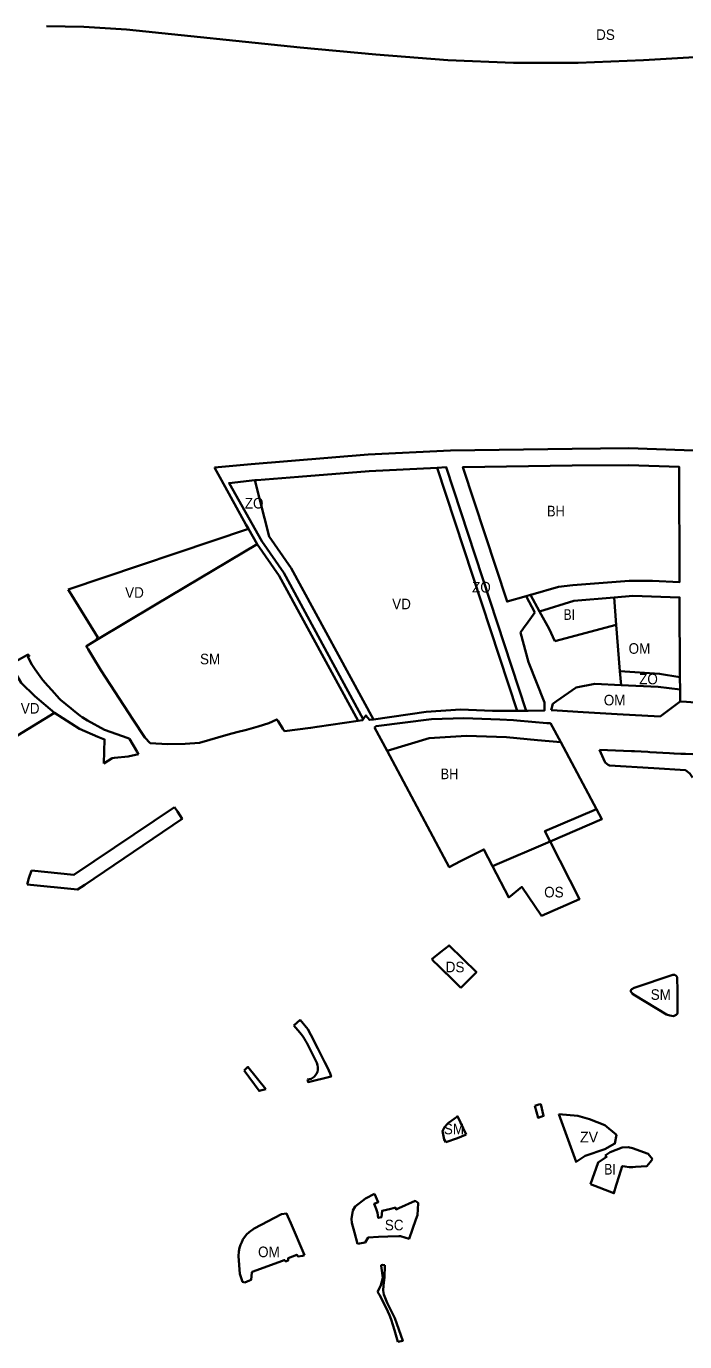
# Model space of a CAD drawing. Extents: x -650971 to -642489, y -1074311 to -1062745.
# Drawn here: x -647822 to -647077, y -1070541 to -1069053 of the extents above; entities that cross this region are included whole.
import ezdxf

# ---------------------------------------------------------------- set-up
doc = ezdxf.new("R2010")
doc.units = 0
doc.header["$LTSCALE"] = 4.8
for name, color, linetype, lineweight in [('1', 7, 'Continuous', 35), ('12', 7, 'Continuous', 35), ('15', 7, 'Continuous', 35), ('17', 7, 'Continuous', 35), ('18', 7, 'Continuous', 35), ('2', 7, 'Continuous', 35), ('24', 7, 'Continuous', 35), ('35', 7, 'Continuous', 35), ('40', 7, 'Continuous', 35), ('42', 7, 'Continuous', 35), ('62', 7, 'Continuous', 35), ('9', 7, 'Continuous', 35)]:
    doc.layers.add(name, color=color, linetype=linetype, lineweight=lineweight)

msp = doc.modelspace()

# ---------------------------------------------------------------- linework, layer by layer
at = {"layer": '1'}
msp.add_lwpolyline([(-647256.061, -1069697.32), (-647277.71, -1069703.421), (-647327.682, -1069551.263), (-647204.208, -1069549.647), (-647140.247, -1069549.071), (-647083.356, -1069551.018), (-647082.761, -1069681.399), (-647113.255, -1069679.966), (-647139.649, -1069679.961), (-647203.374, -1069684.716), (-647219.628, -1069686.746), (-647251.002, -1069695.852), (-647251.13, -1069695.888)], close=True, dxfattribs=at)
for points in [[(-647413.462, -1069872.442), (-647365.866, -1069857.774), (-647323.794, -1069855.468), (-647278.525, -1069857.002), (-647243.231, -1069860.34), (-647217.177, -1069862.57), (-647176.499, -1069938.333)], [(-647294.257, -1070002.745), (-647304.05, -1069983.79), (-647330.5, -1069997.19), (-647343.28, -1070003.81), (-647413.462, -1069872.442)], [(-647176.499, -1069938.333), (-647235, -1069963), (-647229.096, -1069974.658), (-647294.257, -1070002.745)]]:
    msp.add_lwpolyline(points, dxfattribs=at)
at = {"layer": '12'}
for points in [[(-647156.782, -1069698.901), (-647135.585, -1069697.137), (-647082.682, -1069698.791), (-647082.271, -1069788.81)], [(-647082.271, -1069788.81), (-647105.334, -1069785.168), (-647150.138, -1069782.334), (-647154.33, -1069729.69), (-647156.782, -1069698.901)], [(-647228.12, -1069826.33), (-647226.04, -1069819.17), (-647221.87, -1069816.21), (-647199.65, -1069800.69)], [(-647199.65, -1069800.69), (-647178.73, -1069796.4), (-647148.9, -1069797.88)], [(-647148.9, -1069797.88), (-647107.04, -1069799.84), (-647082.206, -1069802.916), (-647082.145, -1069816.321)], [(-647082.145, -1069816.321), (-647104.741, -1069833.568), (-647153.36, -1069830.79), (-647191.66, -1069828.58), (-647221.14, -1069826.761), (-647228.12, -1069826.33)], [(-647574.28, -1070473.46), (-647576.92, -1070473), (-647580.1, -1070463.69), (-647581.54, -1070443.7), (-647581.04, -1070438.4), (-647580.31, -1070434.48), (-647579.22, -1070431.05), (-647577.97, -1070427.92), (-647576.48, -1070425.09), (-647572.37, -1070419.41), (-647569.4, -1070416.55), (-647564.01, -1070412.59), (-647533.1, -1070396.26), (-647527.1, -1070395.72), (-647525.687, -1070399.064)], [(-647525.687, -1070399.064), (-647522.54, -1070406.51), (-647506.95, -1070442.71)], [(-647506.95, -1070442.71), (-647509.22, -1070443.62), (-647514.23, -1070444.18), (-647515.73, -1070442.32), (-647525.45, -1070446.21), (-647525.54, -1070448.89), (-647528.28, -1070449.87), (-647529.19, -1070448.53), (-647529.74, -1070448.27), (-647532.92, -1070449.43), (-647565.11, -1070461.12), (-647565.95, -1070461.58), (-647566.55, -1070462.22), (-647567.32, -1070470.66), (-647569.18, -1070471.4), (-647574.28, -1070473.46)]]:
    msp.add_lwpolyline(points, dxfattribs=at)
at = {"layer": '15'}
msp.add_line((-647518.813, -1070183.069), (-647511.73, -1070176.61), dxfattribs=at)
for points in [[(-647608.81, -1069551.868), (-647567.252, -1069548.083), (-647434.969, -1069537.141), (-647341.697, -1069532.602), (-647204.293, -1069530.647), (-647140.008, -1069530.068), (-647046.325, -1069533.275), (-646986.633, -1069539.757), (-646842.441, -1069555.283)], [(-647446.322, -1069838.338), (-647535.588, -1069674.163), (-647560.36, -1069638.39), (-647570.37, -1069621.18), (-647573.15, -1069616.16), (-647600.891, -1069566.14), (-647606.53, -1069555.98), (-647608.81, -1069551.868)], [(-647356.899, -1069552.034), (-647433.779, -1069556.106), (-647513.66, -1069562.249), (-647560.836, -1069566.036), (-647563.104, -1069566.28)], [(-647256.034, -1069827.107), (-647346.554, -1069551.486), (-647356.899, -1069552.034)], [(-647251.13, -1069695.888), (-647251.002, -1069695.852), (-647219.628, -1069686.746), (-647203.374, -1069684.716), (-647139.649, -1069679.961), (-647113.255, -1069679.966), (-647082.761, -1069681.399), (-647083.356, -1069551.018), (-647140.247, -1069549.071), (-647204.208, -1069549.647), (-647327.682, -1069551.263), (-647277.71, -1069703.421), (-647256.061, -1069697.32), (-647246.42, -1069715.63)], [(-647563.104, -1069566.28), (-647592.199, -1069569.411), (-647555.266, -1069635.207), (-647530.471, -1069671.013), (-647440.459, -1069836.56)], [(-647156.782, -1069698.901), (-647202.181, -1069702.678), (-647240.994, -1069714.513), (-647251.13, -1069695.888)], [(-647082.271, -1069788.81), (-647082.682, -1069698.791), (-647135.585, -1069697.137), (-647156.782, -1069698.901)], [(-647246.42, -1069715.63), (-647253.97, -1069726.27), (-647259.11, -1069733.52), (-647262.46, -1069738.25), (-647253.45, -1069771.95), (-647235.62, -1069817.62)], [(-647060.029, -1069817.854), (-647074.72, -1069816.8), (-647082.145, -1069816.321), (-647082.206, -1069802.916), (-647082.271, -1069788.81)], [(-647235.62, -1069817.62), (-647235.49, -1069826.51), (-647235.48, -1069826.59), (-647236.5, -1069826.63)], [(-647440.459, -1069836.56), (-647441.19, -1069837.6), (-647446.322, -1069838.338)], [(-647427.62, -1069845.94), (-647425.73, -1069844.31), (-647363.21, -1069836.64), (-647326.71, -1069835.46), (-647285.9, -1069836.66), (-647270.71, -1069837.61), (-647266.62, -1069837.86), (-647232.66, -1069841.07), (-647228.77, -1069840.98), (-647217.177, -1069862.57)], [(-647236.5, -1069826.63), (-647253.88, -1069827.12), (-647256.034, -1069827.107)], [(-647217.177, -1069862.57), (-647243.231, -1069860.34), (-647278.525, -1069857.002), (-647323.794, -1069855.468), (-647365.866, -1069857.774), (-647413.462, -1069872.442), (-647427.62, -1069845.94)], [(-647173.23, -1069871.09), (-647136.94, -1069872.55), (-647133.58, -1069872.73), (-647118.77, -1069873.51), (-647116.31, -1069873.65), (-647094.24, -1069874.85), (-647088.93, -1069875.14), (-647088.94, -1069875.34), (-647081.26, -1069875.76), (-647081.25, -1069875.56), (-647076, -1069875.85), (-647034.195, -1069877.629), (-646964.111, -1069878.315), (-646931.67, -1069902.89)], [(-647068.2, -1069902.28), (-647071, -1069897.87), (-647075.97, -1069894.33), (-647111.76, -1069891.77), (-647162.03, -1069888.89), (-647163.55, -1069887.98), (-647166.8, -1069885.63), (-647167.14, -1069884.85), (-647173.23, -1069871.09)], [(-647815.788, -1070007.72), (-647767.622, -1070012.66), (-647654.056, -1069935.903)], [(-647654.056, -1069935.903), (-647650.72, -1069940.96), (-647645.274, -1069949.279), (-647755.356, -1070023.682)], [(-647820.515, -1070023.319), (-647818.81, -1070016.41), (-647815.788, -1070007.72)], [(-647755.356, -1070023.682), (-647763.476, -1070029.17), (-647820.515, -1070023.319)], [(-647511.73, -1070176.61), (-647502.99, -1070186.94), (-647499.68, -1070193.54), (-647491.97, -1070208.95), (-647484.35, -1070223.91)], [(-647503.6, -1070243.95), (-647499.448, -1070243.223), (-647495.889, -1070240.926), (-647493.254, -1070237.6), (-647492.286, -1070235.393), (-647491.767, -1070233.217), (-647491.692, -1070229.974), (-647492.138, -1070227.681), (-647493.13, -1070225.217), (-647504.419, -1070202.575), (-647505.688, -1070200.172), (-647507.054, -1070197.854), (-647509.223, -1070194.61), (-647512.222, -1070190.785), (-647518.813, -1070183.069)], [(-647484.35, -1070223.91), (-647481.01, -1070230.53), (-647477.78, -1070237.42), (-647476.94, -1070240.79), (-647502.82, -1070246.91), (-647503.6, -1070243.95)], [(-647575.15, -1070233.71), (-647570.887, -1070229.877), (-647550.603, -1070254.911)], [(-647550.603, -1070254.911), (-647558.19, -1070256.86), (-647575.15, -1070233.71)], [(-647424.226, -1070484.029), (-647422.285, -1070480.931), (-647420.74, -1070476.57), (-647418.41, -1070468.21), (-647420.13, -1070454.78), (-647420.22, -1070454.02)], [(-647420.22, -1070454.02), (-647418.49, -1070453.76), (-647416.148, -1070454.055)], [(-647416.148, -1070454.055), (-647416.37, -1070468.064), (-647417.482, -1070476.846), (-647418.038, -1070482.516), (-647417.297, -1070487.185), (-647413.552, -1070496.671), (-647404.879, -1070514.114), (-647395.75, -1070539.47), (-647401.35, -1070540.59)], [(-647401.35, -1070540.59), (-647404.96, -1070527.57), (-647408.82, -1070515.49), (-647410.86, -1070510.68), (-647414.6, -1070502.16), (-647422.19, -1070487.75), (-647424.226, -1070484.029)]]:
    msp.add_lwpolyline(points, dxfattribs=at)
for points in [[(-647229.096, -1069974.658), (-647235, -1069963), (-647176.499, -1069938.333), (-647170.546, -1069949.42)], [(-647246.28, -1070273.733), (-647242.06, -1070272.35), (-647239.781, -1070272.031), (-647236.567, -1070285.154), (-647242.698, -1070287.238)]]:
    msp.add_lwpolyline(points, close=True, dxfattribs=at)
at = {"layer": '17'}
for points in [[(-647446.93, -1070429.99), (-647450.51, -1070416.96), (-647453.35, -1070406.09), (-647453.71, -1070401.81), (-647452.17, -1070392.38), (-647449.69, -1070387.83), (-647437.76, -1070378.66), (-647427.8, -1070373.32)], [(-647427.8, -1070373.32), (-647423.57, -1070382.64), (-647427.96, -1070384.64), (-647425.99, -1070390.47), (-647424.54, -1070394.78), (-647423.58, -1070400.59), (-647419.68, -1070399.59), (-647419.08, -1070392.52), (-647409.36, -1070390.24), (-647404, -1070388.84), (-647403.27, -1070390.91), (-647400.22, -1070389.64), (-647381.65, -1070381.45), (-647378.47, -1070383.52)], [(-647378.47, -1070383.52), (-647378.49, -1070383.91), (-647379.3, -1070397.57), (-647381.11, -1070402.45), (-647388.6, -1070424.24), (-647398.21, -1070421.15), (-647400.41, -1070421.08), (-647412.51, -1070421.5), (-647423.38, -1070421.87), (-647434.85, -1070422.64), (-647438.45, -1070428.47), (-647446.93, -1070429.99)]]:
    msp.add_lwpolyline(points, dxfattribs=at)
at = {"layer": '18'}
for points in [[(-647742.36, -1069746.93), (-647674.901, -1069706.701), (-647560.36, -1069638.39)], [(-647560.36, -1069638.39), (-647535.588, -1069674.163), (-647446.322, -1069838.338)], [(-647681.51, -1069863.72), (-647687.45, -1069857.15), (-647700.58, -1069837.2), (-647737.17, -1069780.85), (-647745.84, -1069766.71), (-647751.66, -1069757.12), (-647753.7, -1069753.9), (-647752.32, -1069752.95), (-647742.36, -1069746.93)], [(-647446.322, -1069838.338), (-647492.76, -1069845.02), (-647500.03, -1069846.28), (-647529.5, -1069849.99), (-647531.33, -1069847.23), (-647536.82, -1069838.87), (-647538.34, -1069836.68), (-647547.12, -1069840.87), (-647559.47, -1069844.92), (-647572.63, -1069848.63), (-647583.62, -1069851.13), (-647593.07, -1069853.74), (-647625.83, -1069863.19), (-647641.78, -1069864.26), (-647661.79, -1069864.92), (-647681.51, -1069863.72)], [(-647088.08, -1070125.63), (-647086.49, -1070126.62), (-647085.62, -1070128.24), (-647085.24, -1070144.07), (-647085.17, -1070154.78), (-647084.98, -1070169.29), (-647086.62, -1070170.89), (-647089.47, -1070172.21), (-647093.89, -1070171.55), (-647097.63, -1070170.37), (-647132.95, -1070149.08), (-647136.09, -1070146.97), (-647137.96, -1070144.66), (-647137.99, -1070143.09), (-647136.65, -1070141.75)], [(-647136.65, -1070141.75), (-647133.96, -1070140.44), (-647090.2, -1070125.64), (-647088.08, -1070125.63)], [(-647346.97, -1070315.05), (-647349, -1070312), (-647350.67, -1070302.55), (-647348.677, -1070297.894), (-647345.27, -1070293.99), (-647343.9, -1070292.96), (-647337.56, -1070288.43), (-647336.22, -1070287.43), (-647334.91, -1070286.51), (-647333.87, -1070285.66), (-647324.11, -1070306.21)], [(-647324.11, -1070306.21), (-647324.94, -1070306.63), (-647333.97, -1070310.22), (-647346.97, -1070315.05)]]:
    msp.add_lwpolyline(points, dxfattribs=at)
at = {"layer": '2'}
for points in [[(-647240.994, -1069714.513), (-647202.181, -1069702.678), (-647156.782, -1069698.901), (-647154.33, -1069729.69), (-647223.66, -1069748.26)], [(-647223.66, -1069748.26), (-647230.16, -1069734.42), (-647240.994, -1069714.513)], [(-647183.55, -1070362.35), (-647174.81, -1070338.01), (-647165.36, -1070331.59), (-647167.03, -1070329.81)], [(-647167.03, -1070329.81), (-647161.17, -1070326.29), (-647147.66, -1070321.04), (-647140.83, -1070320.47), (-647135.94, -1070321.54), (-647118.28, -1070328.29), (-647113.37, -1070333.96)], [(-647132.49, -1070342.91), (-647135.62, -1070343.32), (-647139.84, -1070343.16), (-647144.57, -1070342.42), (-647147.6, -1070341.95), (-647151.09, -1070353.15), (-647154.31, -1070363.46), (-647156.9, -1070372.69), (-647183.55, -1070362.35)], [(-647113.37, -1070333.96), (-647116.03, -1070337.68), (-647119.88, -1070342.1), (-647132.49, -1070342.91)]]:
    msp.add_lwpolyline(points, dxfattribs=at)
at = {"layer": '24'}
for points in [[(-646562.49, -1068790.69), (-646575.28, -1068775.04), (-646583.98, -1068766.42), (-646592.53, -1068758.66), (-646601.86, -1068751.01), (-646613.44, -1068743.65), (-646617.991, -1068741.503), (-646673.05, -1068812.491), (-646741.85, -1068895.719), (-646782.784, -1068941.581), (-646829.104, -1068987.917), (-646880.163, -1069024.903), (-646929.186, -1069052.925), (-646978.92, -1069073.93), (-647065.688, -1069087.73), (-647123.648, -1069091.043), (-647197.498, -1069094.255), (-647270.522, -1069094.255), (-647344.902, -1069091.02), (-647426.417, -1069084.624), (-647511.94, -1069076.703), (-647708.401, -1069056.275), (-647756.441, -1069053.207), (-647798.631, -1069052.508)], [(-647362.87, -1070107.74), (-647352.96, -1070099.87), (-647343.454, -1070092.368), (-647312.485, -1070122.583), (-647329.932, -1070140.465)], [(-647329.932, -1070140.465), (-647334.81, -1070135.73), (-647357.4, -1070113.69), (-647359.8, -1070111.34), (-647362.87, -1070107.74)]]:
    msp.add_lwpolyline(points, dxfattribs=at)
at = {"layer": '35'}
for points in [[(-647563.104, -1069566.28), (-647560.836, -1069566.036), (-647513.66, -1069562.249), (-647433.779, -1069556.106), (-647356.899, -1069552.034), (-647266.581, -1069827.042)], [(-647428.993, -1069836.714), (-647521.943, -1069665.763), (-647546.777, -1069629.901), (-647563.104, -1069566.28)], [(-647774.11, -1069689.64), (-647570.37, -1069621.18), (-647560.36, -1069638.39)], [(-647560.36, -1069638.39), (-647674.901, -1069706.701), (-647742.36, -1069746.93)], [(-647742.36, -1069746.93), (-647740.74, -1069744.24), (-647770.38, -1069695.75), (-647772.13, -1069692.89), (-647774.11, -1069689.64)], [(-647827.16, -1069795.32), (-647811.83, -1069810.39), (-647789.55, -1069829.12), (-647831.62, -1069854.99)], [(-647266.581, -1069827.042), (-647270.09, -1069827.02), (-647294.38, -1069826.88), (-647330.46, -1069825.51), (-647369.3, -1069828.22), (-647428.993, -1069836.714)]]:
    msp.add_lwpolyline(points, dxfattribs=at)
at = {"layer": '40'}
msp.add_lwpolyline([(-647219.36, -1070283.36), (-647197.68, -1070285.3), (-647184.77, -1070288.73), (-647167.15, -1070295.69), (-647154.23, -1070306.63), (-647155.89, -1070316.51), (-647167.43, -1070322.66), (-647189.63, -1070330.53), (-647199.79, -1070337.21)], close=True, dxfattribs=at)
at = {"layer": '42'}
msp.add_lwpolyline([(-647356.899, -1069552.034), (-647346.554, -1069551.486), (-647256.034, -1069827.107), (-647266.581, -1069827.042)], close=True, dxfattribs=at)
for points in [[(-647440.459, -1069836.56), (-647530.471, -1069671.013), (-647555.266, -1069635.207), (-647592.199, -1069569.411), (-647563.104, -1069566.28)], [(-647563.104, -1069566.28), (-647546.777, -1069629.901), (-647521.943, -1069665.763), (-647428.993, -1069836.714)], [(-647827.16, -1069795.32), (-647837.93, -1069777.45), (-647838, -1069773.63), (-647826.95, -1069767.48), (-647820.09, -1069763.65), (-647818.73, -1069763.53)], [(-647818.73, -1069763.53), (-647818.28, -1069764.99), (-647819.78, -1069765.84), (-647815.36, -1069774.66), (-647811.65, -1069780.12), (-647809.71, -1069782.79), (-647804.02, -1069791.01), (-647802.92, -1069792.37), (-647797.33, -1069798.65), (-647792.84, -1069803.65), (-647783.96, -1069813.49), (-647782.72, -1069814.46), (-647770.77, -1069824.47), (-647768.63, -1069826.34), (-647760.79, -1069832.61), (-647758.25, -1069834.21), (-647752.25, -1069837.95), (-647732.93, -1069848.5), (-647706.44, -1069857.98), (-647704.99, -1069858.7)], [(-647150.138, -1069782.334), (-647105.334, -1069785.168), (-647082.271, -1069788.81), (-647082.206, -1069802.916)], [(-647082.206, -1069802.916), (-647107.04, -1069799.84), (-647148.9, -1069797.88), (-647150.138, -1069782.334)], [(-647789.55, -1069829.12), (-647811.83, -1069810.39), (-647827.16, -1069795.32)], [(-647733.71, -1069886.65), (-647733.06, -1069859.46), (-647740.46, -1069856.29), (-647761.54, -1069847.24), (-647789.55, -1069829.12)], [(-647428.993, -1069836.714), (-647433.32, -1069837.33), (-647435.36, -1069834.84), (-647437.46, -1069832.27), (-647439.63, -1069835.38), (-647440.459, -1069836.56)], [(-647704.99, -1069858.7), (-647696.25, -1069873.35), (-647694.63, -1069876.07)], [(-647694.63, -1069876.07), (-647706.39, -1069878.81), (-647721.93, -1069880.14), (-647724.35, -1069880.48), (-647733.71, -1069886.65)]]:
    msp.add_lwpolyline(points, dxfattribs=at)
at = {"layer": '9'}
for points in [[(-647294.257, -1070002.745), (-647229.096, -1069974.658), (-647195.933, -1070040.107), (-647238.99, -1070059.05)], [(-647238.99, -1070059.05), (-647261.27, -1070026.12), (-647276, -1070038.08), (-647294.257, -1070002.745)]]:
    msp.add_lwpolyline(points, dxfattribs=at)

# ---------------------------------------------------------------- texts
at = {"layer": '62'}
for s, width, p in [('DS', 0.95, (-647177.118, -1069068.225)), ('ZO', 0.95, (-647574.423, -1069598.188)), ('BH', 0.9, (-647232.617, -1069607.053)), ('VD', 0.95, (-647709.767, -1069699.204)), ('ZO', 0.95, (-647317.423, -1069693.188)), ('VD', 0.95, (-647407.767, -1069712.204)), ('BI', 0.85, (-647213.92, -1069724.163)), ('SM', 0.95, (-647625.077, -1069774.464)), ('OM', 0.95, (-647140.377, -1069762.527)), ('ZO', 0.95, (-647128.473, -1069797.058)), ('OM', 0.95, (-647168.433, -1069820.895)), ('VD', 0.95, (-647827.767, -1069830.204)), ('BH', 0.9, (-647352.947, -1069904.358)), ('OS', 0.95, (-647235.865, -1070038.102)), ('DS', 0.95, (-647347.216, -1070122.778)), ('SM', 0.95, (-647115.357, -1070153.941)), ('SM', 0.95, (-647349.357, -1070305.941)), ('BI', 0.85, (-647167.828, -1070351.569)), ('SC', 0.95, (-647416.06, -1070414.645)), ('OM', 0.95, (-647559.43, -1070445.015))]:
    msp.add_text(s, height=12, dxfattribs=dict(at, width=width)).set_placement(p)
msp.add_text('ZV', height=12, dxfattribs=at).set_placement((-647195.386, -1070315.148))

doc.saveas('drawing.dxf')
